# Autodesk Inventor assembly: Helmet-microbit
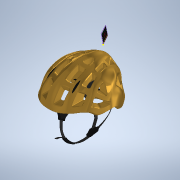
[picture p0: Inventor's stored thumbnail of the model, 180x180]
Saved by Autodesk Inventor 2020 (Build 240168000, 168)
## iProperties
Created: 2021-04
Part Number: Helmet-microbit
Document SubType Name: Assembly
Designer: bruno
Sending System: Autodesk Translation Framework v10.6.0.1341
Preprocessor: ST-DEVELOPER v18.1
Title: C:/Users/admin/Downloads/Ember Diamond bike Helmet.step
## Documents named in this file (6)
- K:\STI2D\IT\P2 Indicateur directionnel\Inventor\Inventor indicateur directionnel\Indicateur directionnel.iam
- K:\STI2D\IT\P2 Indicateur directionnel\Inventor\Inventor indicateur directionnel\Casque\Helmet shell.ipt
- K:\STI2D\IT\P2 Indicateur directionnel\Inventor\Inventor indicateur directionnel\Casque\Strap.iam
- K:\STI2D\IT\P2 Indicateur directionnel\Inventor\Inventor indicateur directionnel\Casque\Strap holder Front.ipt
- K:\STI2D\IT\P2 Indicateur directionnel\Inventor\Inventor indicateur directionnel\Casque\Rear Lock.ipt
- K:\STI2D\IT\P2 Indicateur directionnel\Inventor\Inventor indicateur directionnel\Microbit\microbit.ipt
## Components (5 placed, 5 different names)
1. Helmet shell:1
2. Strap:1 [sub-assembly]
3. Strap holder Front:2
4. Rear Lock:1
5. microbit:1
